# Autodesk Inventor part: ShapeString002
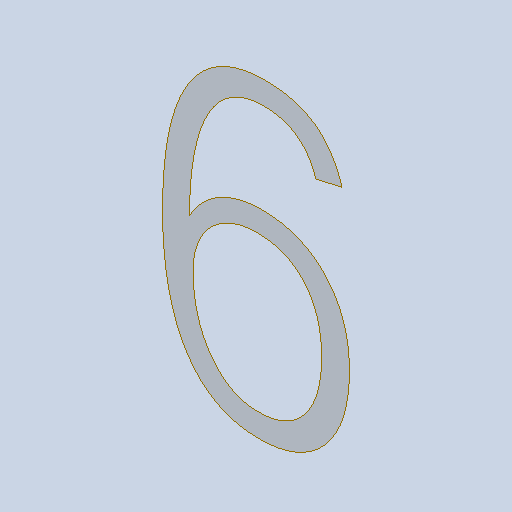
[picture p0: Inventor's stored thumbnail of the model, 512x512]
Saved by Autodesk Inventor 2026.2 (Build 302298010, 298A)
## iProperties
Created: 2026-10
Part Number: ShapeString002
Material: Générique
Document SubType Name: Modeling
Designer: mel
Density: 1 g/cm^3
Appearance: Par défaut
Author: mel
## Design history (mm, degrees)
feature "Composite1"
body "Srf1"
